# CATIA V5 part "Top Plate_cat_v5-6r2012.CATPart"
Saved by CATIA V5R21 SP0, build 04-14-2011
Part number: Top Plate
Bounding box of the stored display mesh (mm): x -125 to 125, y 0 to 150, z 180 to 210
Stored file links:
  D:\CATIA V5R21 E-RESOURCES\CATIA-V5R21\catia-v5r21-Tut\c12-catia-v5r21-tut\c12-catia-v5r21-tut02\Top Plate_cat_v5r21.CATPart
  D:\CATIA V5R21 E-RESOURCES\CATIA-V5R21\catia-v5r21-Tut\c12-catia-v5r21-tut\c12-catia-v5r21-tut02\Assembly.CATProduct
  D:\CATIA V5R21 E-RESOURCES\CATIA-V5R21\catia-v5r21-Tut\c12-catia-v5r21-tut\c12-catia-v5r21-tut02\Bush.CATPart
  D:\CATIA V5R21 E-RESOURCES\CATIA-V5R21\catia-v5r21-Tut\c12-catia-v5r21-tut\c12-catia-v5r21-tut02\Bottom Plate.CATPart
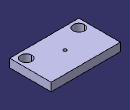
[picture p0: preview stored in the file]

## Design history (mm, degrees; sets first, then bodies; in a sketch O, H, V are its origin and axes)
Set1
  DatumSurface1: linked copy from another document
  DatumCurve1 to DatumCurve5: linked copy from another document
Body1 (main body)
  Sketch1 on face of DatumSurface1, origin (0, 0, 210), H (1, 0, 0), V (0, 1, 0)
    projected line E1 (-125, 0) -> (125, 0) from edge of DatumCurve1
    point P1 (-125, 0)
    point P2 (125, 0)
    projected line E2 (125, 0) -> (125, 150) from edge of DatumCurve2
    point P3 (125, 0)
    point P4 (125, 150)
    projected line E3 (125, 150) -> (-125, 150) from edge of DatumCurve3
    point P5 (125, 150)
    point P6 (-125, 150)
    projected line E4 (-125, 150) -> (-125, 0) from edge of DatumCurve4
    point P7 (-125, 150)
    point P8 (-125, 0)
    projected circle E5 centre (95, 30) radius 20 from edge of DatumCurve5
    circle A1 centre (-95, 30) radius 20
    symmetry: E5 A1 V
    coincidence: P1 P8, P2 P3, P4 P5, P6 P7
  Pad1: profile Sketch1, direction (0, 0, -1), length 30
  Sketch2 on face of Pad1, origin (0, 0, 210), H (1, 0, 0), V (0, 1, 0)
    circle A1 centre (0, 75) radius 6
    point P1 (0, 75)
    reference projected line E1 (-125, 0) -> (125, 0) from edge [face of Pad1 | face of Pad1]
    radius A1 = 6
    distance E1 P1 = 75
    coincidence: P1 V
  Pocket1: profile Sketch2, direction (0, 0, -1), through (limit type 6)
